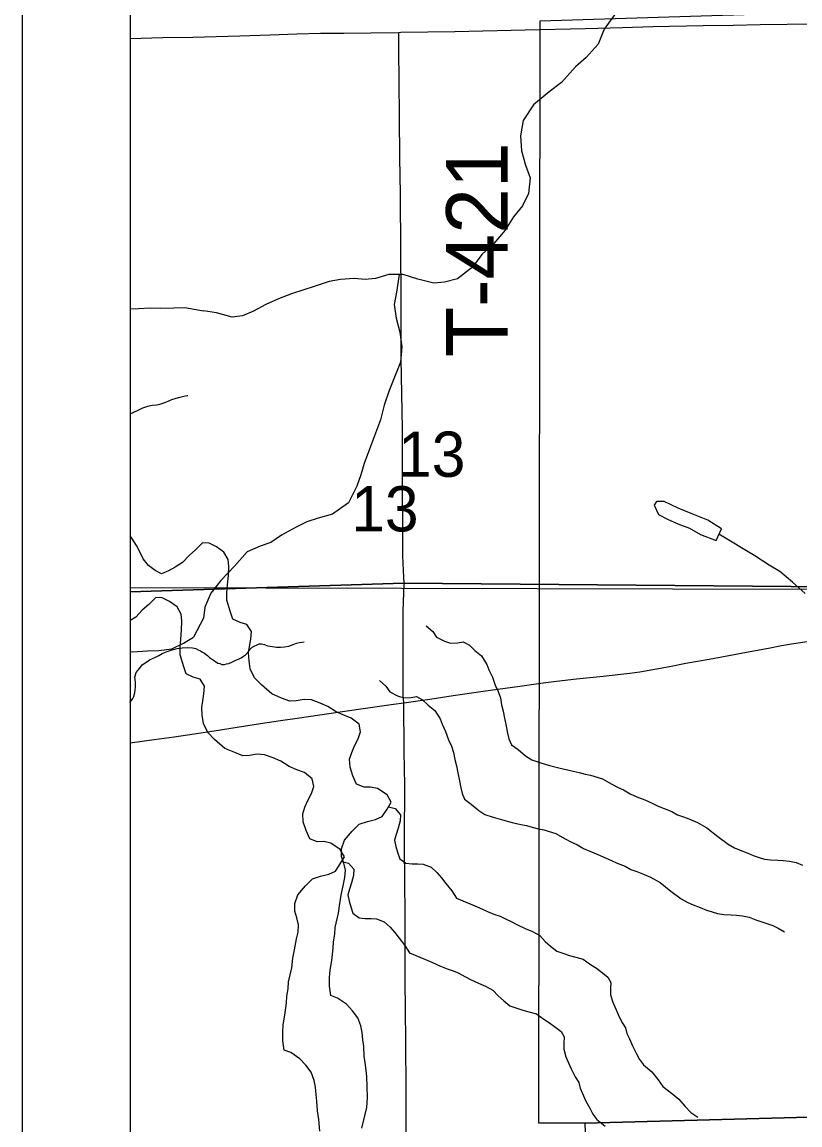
# Model space of a CAD drawing. Extents: x -21.1 to 50.3, y -4.9 to 22.1.
# Drawn here: x 2 to 2.72, y 15.856 to 16.876 of the extents above; entities that cross this region are included whole.
import ezdxf

# ---------------------------------------------------------------- set-up
doc = ezdxf.new("R2010")
doc.units = 0
for name, color, linetype in [('GM_X_Corporation', 7, 'Continuous'), ('GM_X_County', 7, 'Continuous'), ('GM_X_County_Road', 7, 'Continuous'), ('GM_X_Minor_Lake', 7, 'Continuous'), ('GM_X_Minor_River', 7, 'Continuous'), ('GM_X_Rail_Line_Text', 7, 'Continuous'), ('GM_X_Section', 7, 'Continuous'), ('GM_X_Section_Text', 7, 'Continuous'), ('GM_X_Township_Road', 7, 'Continuous'), ('GM_X_Township_Road_Text', 7, 'Continuous'), ('SH_Cut_Line', 7, 'Continuous'), ('SH_Data', 7, 'Continuous')]:
    doc.layers.add(name, color=color, linetype=linetype)

msp = doc.modelspace()

# ---------------------------------------------------------------- linework, layer by layer
at = {"layer": 'GM_X_Corporation'}
msp.add_lwpolyline([(2.1, 17.3693), (2.1, 16.3531), (2.8527, 16.3513), (2.8363, 17.363), (2.8365, 17.3865)], close=True, dxfattribs=at)
at = {"layer": 'GM_X_County'}
msp.add_lwpolyline([(8.9, 14.7464), (8.9, 20.9), (2.1, 20.9), (2.1, 14.1), (8.8932, 14.1)], dxfattribs=at)
at = {"layer": 'GM_X_County_Road'}
for points in [[(2.3484, 16.8666), (2.3505, 16.8667), (2.4002, 16.8675), (2.4654, 16.8688), (2.5213, 16.8703), (2.5555, 16.8712), (2.5834, 16.872), (2.6299, 16.8728), (2.6579, 16.8733), (2.6827, 16.8738), (2.7076, 16.8743), (2.7386, 16.8746), (2.7714, 16.8746), (2.8194, 16.8748), (2.8411, 16.8746), (2.8491, 16.8748)], [(2.1, 16.861), (2.1301, 16.8617), (2.158, 16.8623), (2.2015, 16.8635), (2.2294, 16.8642), (2.2542, 16.8652), (2.276, 16.8657), (2.2977, 16.866), (2.3225, 16.8663), (2.3484, 16.8666)], [(2.3532, 16.2465), (2.3681, 16.2485), (2.3773, 16.2499), (2.3988, 16.2533), (2.4265, 16.2573), (2.4604, 16.262), (2.4819, 16.2649), (2.4943, 16.2664), (2.5128, 16.2685), (2.5375, 16.271), (2.5622, 16.2739), (2.5714, 16.2752), (2.5836, 16.2772), (2.5988, 16.2801), (2.6141, 16.283), (2.6355, 16.2869), (2.6538, 16.2903), (2.6751, 16.2942), (2.6903, 16.2971), (2.7026, 16.2994), (2.7117, 16.301), (2.7363, 16.3048)], [(2.1, 16.2096), (2.1223, 16.2126), (2.1407, 16.2151), (2.153, 16.2169), (2.1776, 16.2207), (2.1991, 16.2239), (2.2206, 16.2272), (2.239, 16.23), (2.2544, 16.2322), (2.2943, 16.2382), (2.322, 16.242), (2.3435, 16.2451), (2.3532, 16.2465)]]:
    msp.add_lwpolyline(points, dxfattribs=at)
at = {"layer": 'GM_X_Minor_Lake'}
for points in [[(2.6469, 16.4073), (2.6344, 16.4154), (2.6204, 16.4211), (2.6068, 16.4265), (2.594, 16.4327), (2.5867, 16.4327), (2.5848, 16.4293), (2.5886, 16.4206), (2.5969, 16.4164), (2.6067, 16.4121), (2.6173, 16.4079), (2.6275, 16.4021), (2.6419, 16.3967)], [(2.6419, 16.3967), (2.6469, 16.4073)]]:
    msp.add_lwpolyline(points, dxfattribs=at)
at = {"layer": 'GM_X_Minor_River'}
for points in [[(2.548, 16.8829), (2.5384, 16.8697), (2.533, 16.8557), (2.5219, 16.8433), (2.512, 16.8346), (2.499, 16.8203), (2.4875, 16.8116), (2.473, 16.7996), (2.4635, 16.7852), (2.4611, 16.7708), (2.4621, 16.7571), (2.4658, 16.7438), (2.4699, 16.732), (2.4683, 16.7176), (2.4629, 16.7063), (2.4545, 16.6961), (2.4468, 16.6836), (2.4365, 16.6712), (2.4254, 16.661), (2.4166, 16.6493), (2.4029, 16.6387), (2.3907, 16.6354), (2.3809, 16.6347), (2.3661, 16.6382), (2.3525, 16.6425), (2.3392, 16.6425), (2.327, 16.6388), (2.3175, 16.6381), (2.3073, 16.6389), (2.2944, 16.6379), (2.2841, 16.6361), (2.2701, 16.6316), (2.2605, 16.6286), (2.2491, 16.6249), (2.2373, 16.62), (2.2255, 16.6148), (2.2141, 16.6088), (2.2038, 16.6043), (2.1944, 16.6032), (2.18, 16.6071), (2.1678, 16.6091)], [(2.3487, 16.6425), (2.3463, 16.6262), (2.3443, 16.6148), (2.3461, 16.6023), (2.3495, 16.5894), (2.3513, 16.5757), (2.35, 16.5617), (2.3446, 16.5477), (2.3396, 16.5352), (2.335, 16.5219), (2.3315, 16.5083), (2.3261, 16.4935), (2.3214, 16.481), (2.3164, 16.4678), (2.3133, 16.4572), (2.3098, 16.447), (2.3018, 16.4314), (2.2873, 16.4209), (2.274, 16.4172), (2.2633, 16.4138), (2.2534, 16.409), (2.2401, 16.4015), (2.2302, 16.3947), (2.2203, 16.3913), (2.2081, 16.3861), (2.1966, 16.3729), (2.184, 16.3597), (2.1745, 16.348), (2.1691, 16.3348), (2.1679, 16.3249), (2.1587, 16.3072)], [(2.1, 16.6108), (2.1076, 16.6112), (2.1186, 16.6119), (2.1281, 16.6115), (2.1403, 16.6118), (2.1505, 16.6121), (2.1678, 16.6091)], [(2.1, 16.5137), (2.1033, 16.5154), (2.1075, 16.5172), (2.1117, 16.5194), (2.1163, 16.5208), (2.1205, 16.5219), (2.1243, 16.5222), (2.1266, 16.5225), (2.1293, 16.5233), (2.1331, 16.5247), (2.1384, 16.5269), (2.1446, 16.529), (2.1495, 16.5301), (2.1526, 16.5308), (2.153, 16.5308), (2.1533, 16.5308)], [(2.3144, 15.8529), (2.3189, 15.8723), (2.3196, 15.8815), (2.3192, 15.8913), (2.3188, 15.9009), (2.3177, 15.9115), (2.3165, 15.9195), (2.3161, 15.9286), (2.3153, 15.9347), (2.3146, 15.9415), (2.3134, 15.9476), (2.3107, 15.9552), (2.3058, 15.9617), (2.3001, 15.9677), (2.2918, 15.9734), (2.2857, 15.9757), (2.2845, 15.9844), (2.2845, 15.9924), (2.2849, 15.9993), (2.2864, 16.008), (2.2879, 16.0194), (2.2882, 16.0255), (2.2894, 16.0324), (2.2897, 16.0388), (2.2927, 16.0518), (2.2938, 16.0609), (2.2953, 16.0685), (2.2972, 16.0788), (2.2987, 16.0849), (2.2991, 16.0917), (2.2976, 16.0982), (2.2956, 16.1042), (2.2956, 16.1115), (2.2983, 16.1195), (2.3054, 16.1278), (2.3119, 16.1343), (2.3194, 16.1366), (2.327, 16.1385), (2.3331, 16.1412), (2.3376, 16.1481), (2.3414, 16.1545), (2.3376, 16.1614), (2.3289, 16.1671), (2.3224, 16.1686), (2.3163, 16.1686), (2.3095, 16.1712), (2.3061, 16.1788), (2.3034, 16.1868), (2.303, 16.1944), (2.3049, 16.2005), (2.3075, 16.2066), (2.3109, 16.213), (2.3132, 16.2195), (2.3117, 16.2267), (2.3045, 16.2324), (2.2976, 16.2351), (2.2904, 16.2381), (2.2828, 16.243), (2.2756, 16.246), (2.2677, 16.2491), (2.2608, 16.2494), (2.2536, 16.2483), (2.2476, 16.2479), (2.24, 16.2509), (2.2309, 16.2547), (2.2214, 16.263), (2.215, 16.2695), (2.2111, 16.2778), (2.21, 16.2854), (2.2096, 16.2926), (2.2103, 16.2987), (2.2115, 16.3052), (2.2122, 16.3124), (2.208, 16.3189), (2.2016, 16.3208), (2.1951, 16.3238), (2.1928, 16.3303), (2.1894, 16.3413), (2.1894, 16.3481), (2.1901, 16.3557), (2.1909, 16.3641), (2.1912, 16.3725), (2.1905, 16.3789), (2.1867, 16.3858), (2.1798, 16.3907), (2.173, 16.3941), (2.1669, 16.3945), (2.1605, 16.388), (2.1545, 16.3826), (2.1484, 16.3762), (2.1416, 16.372), (2.1355, 16.3685), (2.1291, 16.3658), (2.123, 16.3689), (2.117, 16.3734), (2.112, 16.3795), (2.1094, 16.3856), (2.1059, 16.392), (2.1014, 16.3989), (2.1, 16.401)], [(2.7243, 16.3477), (2.7126, 16.358), (2.7009, 16.3679), (2.6911, 16.3737), (2.6779, 16.3825), (2.6446, 16.4025)], [(2.2755, 15.8503), (2.2744, 15.861), (2.2732, 15.869), (2.2728, 15.8781), (2.2721, 15.8842), (2.2713, 15.891), (2.2701, 15.8971), (2.2675, 15.9047), (2.2625, 15.9112), (2.2568, 15.9172), (2.2485, 15.9229), (2.2424, 15.9252), (2.2413, 15.9339), (2.2412, 15.9419), (2.2416, 15.9487), (2.2431, 15.9575), (2.2446, 15.9689), (2.2449, 15.975), (2.2461, 15.9818), (2.2464, 15.9883), (2.2494, 16.0012), (2.2506, 16.0104), (2.2521, 16.018), (2.2539, 16.0283), (2.2554, 16.0343), (2.2558, 16.0412), (2.2543, 16.0476), (2.2524, 16.0537), (2.2523, 16.0609), (2.255, 16.0689), (2.2622, 16.0773), (2.2686, 16.0838), (2.2762, 16.0861), (2.2837, 16.088), (2.2898, 16.0907), (2.2943, 16.0976), (2.2981, 16.104), (2.2943, 16.1109), (2.2856, 16.1165), (2.2791, 16.1181), (2.2731, 16.118), (2.2662, 16.1207), (2.2628, 16.1283), (2.2601, 16.1363), (2.2597, 16.1439), (2.2616, 16.15), (2.2643, 16.156), (2.2677, 16.1625), (2.2699, 16.169), (2.2684, 16.1762), (2.2612, 16.1819), (2.2543, 16.1845), (2.2471, 16.1876), (2.2395, 16.1925), (2.2323, 16.1955), (2.2244, 16.1985), (2.2176, 16.1989), (2.2104, 16.1977), (2.2043, 16.1974), (2.1967, 16.2004), (2.1876, 16.2042), (2.1781, 16.2125), (2.1717, 16.2189), (2.1679, 16.2273), (2.1667, 16.2349), (2.1663, 16.2421), (2.1671, 16.2482), (2.1682, 16.2547), (2.1689, 16.2619), (2.1647, 16.2684), (2.1583, 16.2703), (2.1518, 16.2733), (2.1496, 16.2797), (2.1461, 16.2908), (2.1461, 16.2976), (2.1468, 16.3052), (2.1476, 16.3136), (2.1479, 16.3219), (2.1472, 16.3284), (2.1434, 16.3352), (2.1365, 16.3402), (2.1297, 16.3436), (2.1236, 16.3439), (2.1172, 16.3375), (2.1112, 16.3321), (2.1051, 16.3256), (2.1, 16.3225)], [(2.3738, 16.3177), (2.3799, 16.3124), (2.3834, 16.3071), (2.3906, 16.3034), (2.3963, 16.3015), (2.4032, 16.302), (2.4081, 16.3028), (2.4138, 16.2998), (2.4188, 16.2949), (2.4249, 16.29), (2.43, 16.282), (2.4319, 16.2771), (2.435, 16.2703), (2.4377, 16.2627), (2.4404, 16.257), (2.4424, 16.251), (2.4436, 16.2445), (2.4451, 16.2388), (2.4463, 16.2324), (2.4479, 16.2248), (2.4491, 16.2183), (2.4503, 16.213), (2.4526, 16.2077), (2.4588, 16.2032), (2.4656, 16.1975), (2.4714, 16.1938), (2.479, 16.1912), (2.4878, 16.1886), (2.4965, 16.1864), (2.5045, 16.1845), (2.5099, 16.1834), (2.5152, 16.182), (2.5209, 16.1805), (2.5259, 16.1794), (2.5369, 16.1761), (2.545, 16.1716), (2.5514, 16.1682), (2.5564, 16.166), (2.5625, 16.1622), (2.5686, 16.1596), (2.5759, 16.1566), (2.5835, 16.1532), (2.5885, 16.151), (2.5938, 16.1488), (2.6011, 16.1458), (2.6064, 16.1428), (2.6118, 16.1409), (2.6167, 16.1391), (2.6247, 16.1357), (2.6335, 16.1308), (2.6435, 16.1229), (2.653, 16.1158), (2.6591, 16.1124), (2.6641, 16.1102), (2.6706, 16.1076), (2.6763, 16.1053), (2.6817, 16.1035), (2.6866, 16.102), (2.6923, 16.1013), (2.6992, 16.1009), (2.7041, 16.1006), (2.7098, 16.0999), (2.7159, 16.0988), (2.722, 16.0962)], [(2.1, 16.2938), (2.1021, 16.2935), (2.1161, 16.2945), (2.1264, 16.2948), (2.1385, 16.2963), (2.1492, 16.3016), (2.1587, 16.3072)], [(2.2028, 16.288), (2.2047, 16.2895), (2.2066, 16.2909), (2.2094, 16.2939), (2.2109, 16.2962), (2.2129, 16.298), (2.2194, 16.301), (2.2216, 16.3009), (2.2243, 16.3005), (2.2269, 16.2993), (2.2315, 16.2985), (2.2353, 16.298), (2.2391, 16.2979), (2.2429, 16.2982), (2.2467, 16.2989), (2.2509, 16.3004), (2.254, 16.3015), (2.2567, 16.3022), (2.2589, 16.3025), (2.2608, 16.3028)], [(2.1, 16.2468), (2.1001, 16.247), (2.1025, 16.2504), (2.1033, 16.2522), (2.1041, 16.2545), (2.1045, 16.2579), (2.105, 16.2617), (2.105, 16.2651), (2.1047, 16.2682), (2.1044, 16.2701), (2.1056, 16.2746), (2.1087, 16.2783), (2.111, 16.2817), (2.1153, 16.2843), (2.118, 16.2861), (2.1207, 16.2876), (2.1233, 16.2887), (2.1264, 16.2902), (2.1295, 16.292), (2.1341, 16.2938), (2.1387, 16.2956), (2.1436, 16.2967), (2.1482, 16.2973), (2.1528, 16.2976), (2.1577, 16.2972), (2.1607, 16.2967), (2.163, 16.2956), (2.1649, 16.2944), (2.1668, 16.2932), (2.1686, 16.2924), (2.1716, 16.2901), (2.1735, 16.2885), (2.1761, 16.2866), (2.1788, 16.2846), (2.181, 16.2831), (2.1829, 16.2827), (2.1848, 16.2819), (2.1871, 16.2818), (2.189, 16.2825), (2.1913, 16.2829), (2.1947, 16.2843), (2.1978, 16.2858), (2.2001, 16.2869), (2.2028, 16.288)], [(2.3305, 16.2672), (2.3366, 16.2619), (2.3401, 16.2566), (2.3473, 16.2529), (2.353, 16.251), (2.3599, 16.2515), (2.3648, 16.2523), (2.3705, 16.2493), (2.3755, 16.2444), (2.3817, 16.2395), (2.3867, 16.2315), (2.3886, 16.2266), (2.3917, 16.2198), (2.3944, 16.2122), (2.3971, 16.2065), (2.3991, 16.2004), (2.4003, 16.194), (2.4019, 16.1883), (2.4031, 16.1818), (2.4046, 16.1743), (2.4058, 16.1678), (2.407, 16.1625), (2.4093, 16.1572), (2.4155, 16.1527), (2.4224, 16.147), (2.4281, 16.1433), (2.4357, 16.1407), (2.4445, 16.1381), (2.4533, 16.1359), (2.4613, 16.134), (2.4666, 16.1329), (2.4719, 16.1314), (2.4776, 16.13), (2.4826, 16.1289), (2.4936, 16.1255), (2.5017, 16.121), (2.5082, 16.1177), (2.5131, 16.1154), (2.5192, 16.1117), (2.5253, 16.1091), (2.5326, 16.1061), (2.5402, 16.1027), (2.5452, 16.1005), (2.5505, 16.0982), (2.5578, 16.0953), (2.5631, 16.0923), (2.5685, 16.0904), (2.5734, 16.0885), (2.5814, 16.0852), (2.5902, 16.0803), (2.6002, 16.0724), (2.6097, 16.0653), (2.6159, 16.0619), (2.6208, 16.0597), (2.6273, 16.057), (2.633, 16.0548), (2.6384, 16.053), (2.6433, 16.0515), (2.649, 16.0508), (2.6559, 16.0504), (2.6608, 16.0501), (2.6665, 16.0494), (2.6726, 16.0483), (2.6787, 16.0457), (2.6871, 16.0431), (2.6944, 16.0405), (2.6993, 16.0379), (2.7051, 16.0345)], [(2.3389, 16.1503), (2.3451, 16.1486), (2.3501, 16.143), (2.3498, 16.1373), (2.348, 16.1304), (2.3461, 16.1247), (2.3446, 16.1194), (2.3458, 16.1137), (2.3474, 16.1083), (2.3493, 16.1023), (2.3551, 16.0981), (2.3608, 16.0974), (2.3661, 16.0975), (2.3711, 16.0971), (2.3783, 16.0945), (2.3837, 16.0896), (2.3879, 16.0847), (2.3921, 16.0794), (2.3975, 16.0726), (2.4017, 16.0658), (2.4113, 16.0617), (2.4166, 16.0595), (2.4231, 16.0569), (2.4304, 16.0535), (2.4365, 16.0509), (2.4422, 16.049), (2.4472, 16.0468), (2.4529, 16.0438), (2.4582, 16.0412), (2.4655, 16.0378), (2.472, 16.0348), (2.4788, 16.0311), (2.4838, 16.0258), (2.4888, 16.0213), (2.4946, 16.0168), (2.501, 16.0145), (2.5064, 16.0127), (2.5121, 16.0112), (2.519, 16.0094), (2.5258, 16.0045), (2.5312, 16.0011), (2.5369, 15.9966), (2.5419, 15.9928), (2.5446, 15.9879), (2.5443, 15.9818), (2.5443, 15.9765), (2.5463, 15.9697), (2.5513, 15.9583), (2.5548, 15.9511), (2.5583, 15.9458), (2.5595, 15.9405), (2.5618, 15.9356), (2.5645, 15.9291), (2.5684, 15.9219), (2.5711, 15.9166), (2.5749, 15.9117), (2.5826, 15.9053), (2.5883, 15.8978), (2.5926, 15.8917), (2.6021, 15.8846), (2.6075, 15.88), (2.6133, 15.8732), (2.6186, 15.8676), (2.6251, 15.8631)], [(2.2956, 16.0998), (2.3019, 16.0981), (2.3069, 16.0925), (2.3065, 16.0868), (2.3047, 16.0799), (2.3028, 16.0742), (2.3013, 16.0688), (2.3025, 16.0631), (2.3041, 16.0578), (2.3061, 16.0518), (2.3118, 16.0476), (2.3175, 16.0469), (2.3228, 16.047), (2.3278, 16.0466), (2.335, 16.044), (2.3404, 16.0391), (2.3446, 16.0342), (2.3488, 16.0289), (2.3542, 16.0221), (2.3585, 16.0153), (2.368, 16.0112), (2.3733, 16.009), (2.3798, 16.0064), (2.3871, 16.003), (2.3932, 16.0004), (2.3989, 15.9985), (2.4039, 15.9963), (2.4096, 15.9933), (2.4149, 15.9907), (2.4222, 15.9873), (2.4287, 15.9843), (2.4356, 15.9806), (2.4405, 15.9753), (2.4455, 15.9708), (2.4513, 15.9662), (2.4577, 15.964), (2.4631, 15.9622), (2.4688, 15.9607), (2.4757, 15.9588), (2.4825, 15.954), (2.4879, 15.9506), (2.4936, 15.9461), (2.4986, 15.9423), (2.5013, 15.9374), (2.501, 15.9313), (2.501, 15.926), (2.503, 15.9191), (2.508, 15.9078), (2.5115, 15.9006), (2.515, 15.8953), (2.5162, 15.89), (2.5185, 15.885), (2.5212, 15.8786), (2.5251, 15.8714), (2.5278, 15.8661), (2.5316, 15.8612), (2.5393, 15.8548)]]:
    msp.add_lwpolyline(points, dxfattribs=at)
at = {"layer": 'GM_X_Rail_Line_Text'}
msp.add_lwpolyline([(2.8583, 15.8417), (2.8581, 15.8603), (2.8572, 15.9223), (2.857, 15.9316), (2.8567, 15.9502), (2.8564, 16.006), (2.8563, 16.0308), (2.8561, 16.0588), (2.8559, 16.096), (2.8554, 16.1457), (2.8552, 16.1768), (2.8549, 16.2016), (2.8551, 16.2233), (2.8554, 16.2486), (2.8554, 16.278), (2.8552, 16.303), (2.8548, 16.3167), (2.8549, 16.3231), (2.855, 16.3256), (2.8548, 16.3349), (2.8547, 16.3527), (2.3532, 16.3572), (2.1, 16.3492), (2.1, 14.1)], dxfattribs=at)
at = {"layer": 'GM_X_Section'}
for points in [[(3.4856, 16.8942), (3.4867, 15.8836), (2.5208, 15.8578), (2.478, 15.8578), (2.4791, 16.8774), (2.9755, 16.8927)], [(3.5076, 15.884), (3.5576, 14.829), (2.5595, 14.8074), (2.5208, 15.8578), (3.4867, 15.8836)]]:
    msp.add_lwpolyline(points, close=True, dxfattribs=at)
at = {"layer": 'GM_X_Township_Road'}
for points in [[(2.3534, 16.3567), (2.3528, 16.369), (2.3522, 16.3823), (2.3519, 16.4659), (2.3518, 16.5), (2.3508, 16.565), (2.3507, 16.596), (2.3507, 16.6239), (2.3504, 16.6642), (2.3499, 16.7169), (2.3495, 16.751), (2.3491, 16.7881), (2.3489, 16.8222), (2.3486, 16.8495), (2.3484, 16.8625), (2.3484, 16.8666)], [(2.3532, 16.2465), (2.3526, 16.2538), (2.3526, 16.2696), (2.3526, 16.3066), (2.3526, 16.3312), (2.3534, 16.3567)], [(2.3553, 15.8315), (2.3552, 15.8688), (2.3552, 15.8843), (2.3552, 15.8967), (2.355, 15.9246), (2.3549, 15.9402), (2.3548, 15.9557), (2.3544, 15.996), (2.3543, 16.0085), (2.3543, 16.024), (2.3544, 16.0457), (2.3544, 16.0581), (2.3542, 16.0739), (2.3539, 16.1206), (2.3541, 16.1702), (2.3534, 16.201), (2.3533, 16.2072), (2.3532, 16.2414), (2.3532, 16.2465)]]:
    msp.add_lwpolyline(points, dxfattribs=at)
at = {"layer": 'SH_Cut_Line'}
for points in [[(8.9, 20.9), (2.1, 20.9), (2.1, 16.3492), (2.3532, 16.3572), (2.8547, 16.3527), (2.9841, 16.3439), (3.8594, 16.3662)], [(3.8594, 16.3662), (2.9841, 16.3439), (2.8547, 16.3527), (2.3532, 16.3572), (2.1, 16.3492), (2.1, 14.1), (8.9, 14.1)]]:
    msp.add_lwpolyline(points, dxfattribs=at)
at = {"layer": 'SH_Data'}
msp.add_line((2, 21), (2, 14), dxfattribs=at)

# ---------------------------------------------------------------- texts
at = {"layer": 'GM_X_Section_Text'}
for p in [(2.3478, 16.4555), (2.3045, 16.405)]:
    msp.add_text('13', height=0.04186, rotation=0, dxfattribs=at).set_placement(p)
at = {"layer": 'GM_X_Township_Road_Text'}
msp.add_text('T-421', height=0.05682, rotation=90, dxfattribs=at).set_placement((2.4491, 16.5663))

doc.saveas('drawing.dxf')
